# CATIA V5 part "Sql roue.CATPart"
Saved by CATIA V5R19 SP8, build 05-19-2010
Part number: Sql roue
Publications: "Droite.1", "Plan.1", "Droite.2"
Bounding box of the stored display mesh (mm): x 480 to 520, y 120 to 120, z -310 to -110
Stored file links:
  C:\Users\ThinkMotion\Desktop\EU_thinkMotion\iao\IAO_MMS_Groupe3\rdalborgo\rdalborgo\Sql roue.CATPart
  C:\Users\ThinkMotion\Desktop\EU_thinkMotion\iao\IAO_MMS_Groupe3\rdalborgo\rdalborgo\Sql train.CATProduct
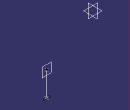
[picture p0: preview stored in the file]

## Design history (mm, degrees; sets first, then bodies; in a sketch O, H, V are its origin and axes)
Set1
  Point1 "Centre roue": linked copy from another document
  Point2 "Ext roue": linked copy from another document
  Plane1: linked copy from another document
  Plane2: linked copy from another document
Set2
  Line1: type PtPt, FirstPoint Point1, SecondPoint Point2
  Plane3: type OffsetPt, RefPlane Plane1, RefPoint Point2
  Line2: type Normal, RefPoint Point1, RefSkin Plane2, Start -20, End 20
Body1 (main body)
